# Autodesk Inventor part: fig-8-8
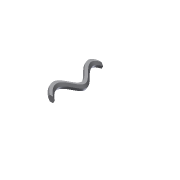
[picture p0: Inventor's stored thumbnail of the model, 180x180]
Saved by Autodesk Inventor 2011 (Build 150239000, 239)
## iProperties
Created: 2006-01
Part Number: fig-8-8
Document SubType Name: Modeling
Designer: CADCIM
Density: 1 g/cm^3
Author: CADCIM
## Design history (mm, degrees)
sketch "Sketch1"
  geometry: 5 further points
  constraints: 5 other
sketch "Sketch2"
  geometry: L1 (-4.728, 0)-(-2.364, 4.094); L2 (-2.364, 4.094)-(2.364, 4.094); L3 (2.364, 4.094)-(4.728, 0); L4 (4.728, 0)-(2.364, -4.094); L5 (2.364, -4.094)-(-2.364, -4.094); L6 (-2.364, -4.094)-(-4.728, 0); 1 further point
  constraints: 12 end point, 13 other
sweep "Sweep4" sketch "Sketch1", "Sketch2" dims "d3" = 0
body "Solid2"
